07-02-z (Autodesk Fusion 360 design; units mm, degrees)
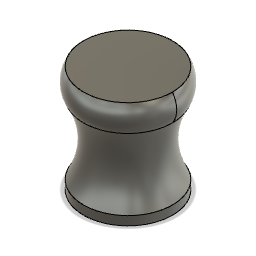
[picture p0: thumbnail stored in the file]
sketch "スケッチ1" plane through (0, 0, 0) normal (0, 1, 0) x axis (1, 0, 0)
  circle C1 centre (0, 0) radius 25
  point P1 (0, 0)
  point P2 (0, 0)
  coincident P1 P2
  dimension "d1" diameter C1 = 50
extrude "押し出し" new body sketch "スケッチ1" along normal blind 5
work_plane "作業平面1" AlongDistance 20
sketch "スケッチ2" plane through (0, 25, 0) normal (0, 1, 0) x axis (1, 0, 0)
  circle C1 centre (0, 0) radius 20
  point P1 (0, 0)
  point P2 (0, 0)
  coincident P1 P2
  dimension "d5" diameter C1 = 40
work_plane "作業平面2" AlongDistance 20
sketch "スケッチ3" plane through (0, 45, 0) normal (0, 1, 0) x axis (1, 0, 0)
  circle C1 centre (0, 0) radius 25
loft "ロフト1" sketch "スケッチ2" + "スケッチ3"
work_plane "作業平面3" AlongDistance 15
sketch "スケッチ4" plane through (0, 60, 0) normal (0, 1, 0) x axis (1, 0, 0)
  circle C1 centre (0, 0) radius 25
sketch "スケッチ5" plane through (0, 0, 0) normal (0, 0, 1) x axis (1, 0, 0)
  line L1 (-25, 60) -> (25, 60)
  line L2 (25, 45) -> (-25, 45)
  arc A1 centre (-14.3816, 52.5) radius 13 clockwise from (-25, 45) to (-25, 60)
  arc A2 centre (14.3816, 52.5) radius 13 clockwise from (25, 60) to (25, 45)
  point P2 (-25, 60)
  point P9 (-25, 60)
  point P3 (-25, 45)
  point P10 (-25, 45)
  point P5 (25, 60)
  point P8 (25, 60)
  point P6 (25, 45)
  point P11 (25, 45)
  coincident P2 P9
  coincident P3 P10
  coincident P5 P8
  coincident P6 P11
  equal A1 A2
  dimension "d8" radius A1 = 13
sketch "スケッチ6" plane through (0, 0, 0) normal (1, 0, 0) x axis (0, 0, -1)
  line L1 (-25, 60) -> (25, 60)
  line L2 (25, 45) -> (-25, 45)
  arc A1 centre (-14.3816, 52.5) radius 13 clockwise from (-25, 45) to (-25, 60)
  arc A2 centre (14.3816, 52.5) radius 13 clockwise from (25, 60) to (25, 45)
  point P2 (-25, 60)
  point P9 (-25, 60)
  point P3 (-25, 45)
  point P10 (-25, 45)
  point P6 (25, 45)
  point P11 (25, 45)
  point P5 (25, 60)
  point P8 (25, 60)
  coincident P2 P9
  coincident P3 P10
  coincident P6 P11
  coincident P5 P8
  equal A1 A2
  dimension "d9" radius A1 = 13
loft "ロフト2" sketch "スケッチ4"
